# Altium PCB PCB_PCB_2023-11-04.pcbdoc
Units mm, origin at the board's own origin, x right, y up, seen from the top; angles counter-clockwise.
Board outline 154.66 x 127.63 mm, 2 copper layers (Top Layer, Bottom Layer); 91 components, 86 nets, 342 pads, 162 vias.
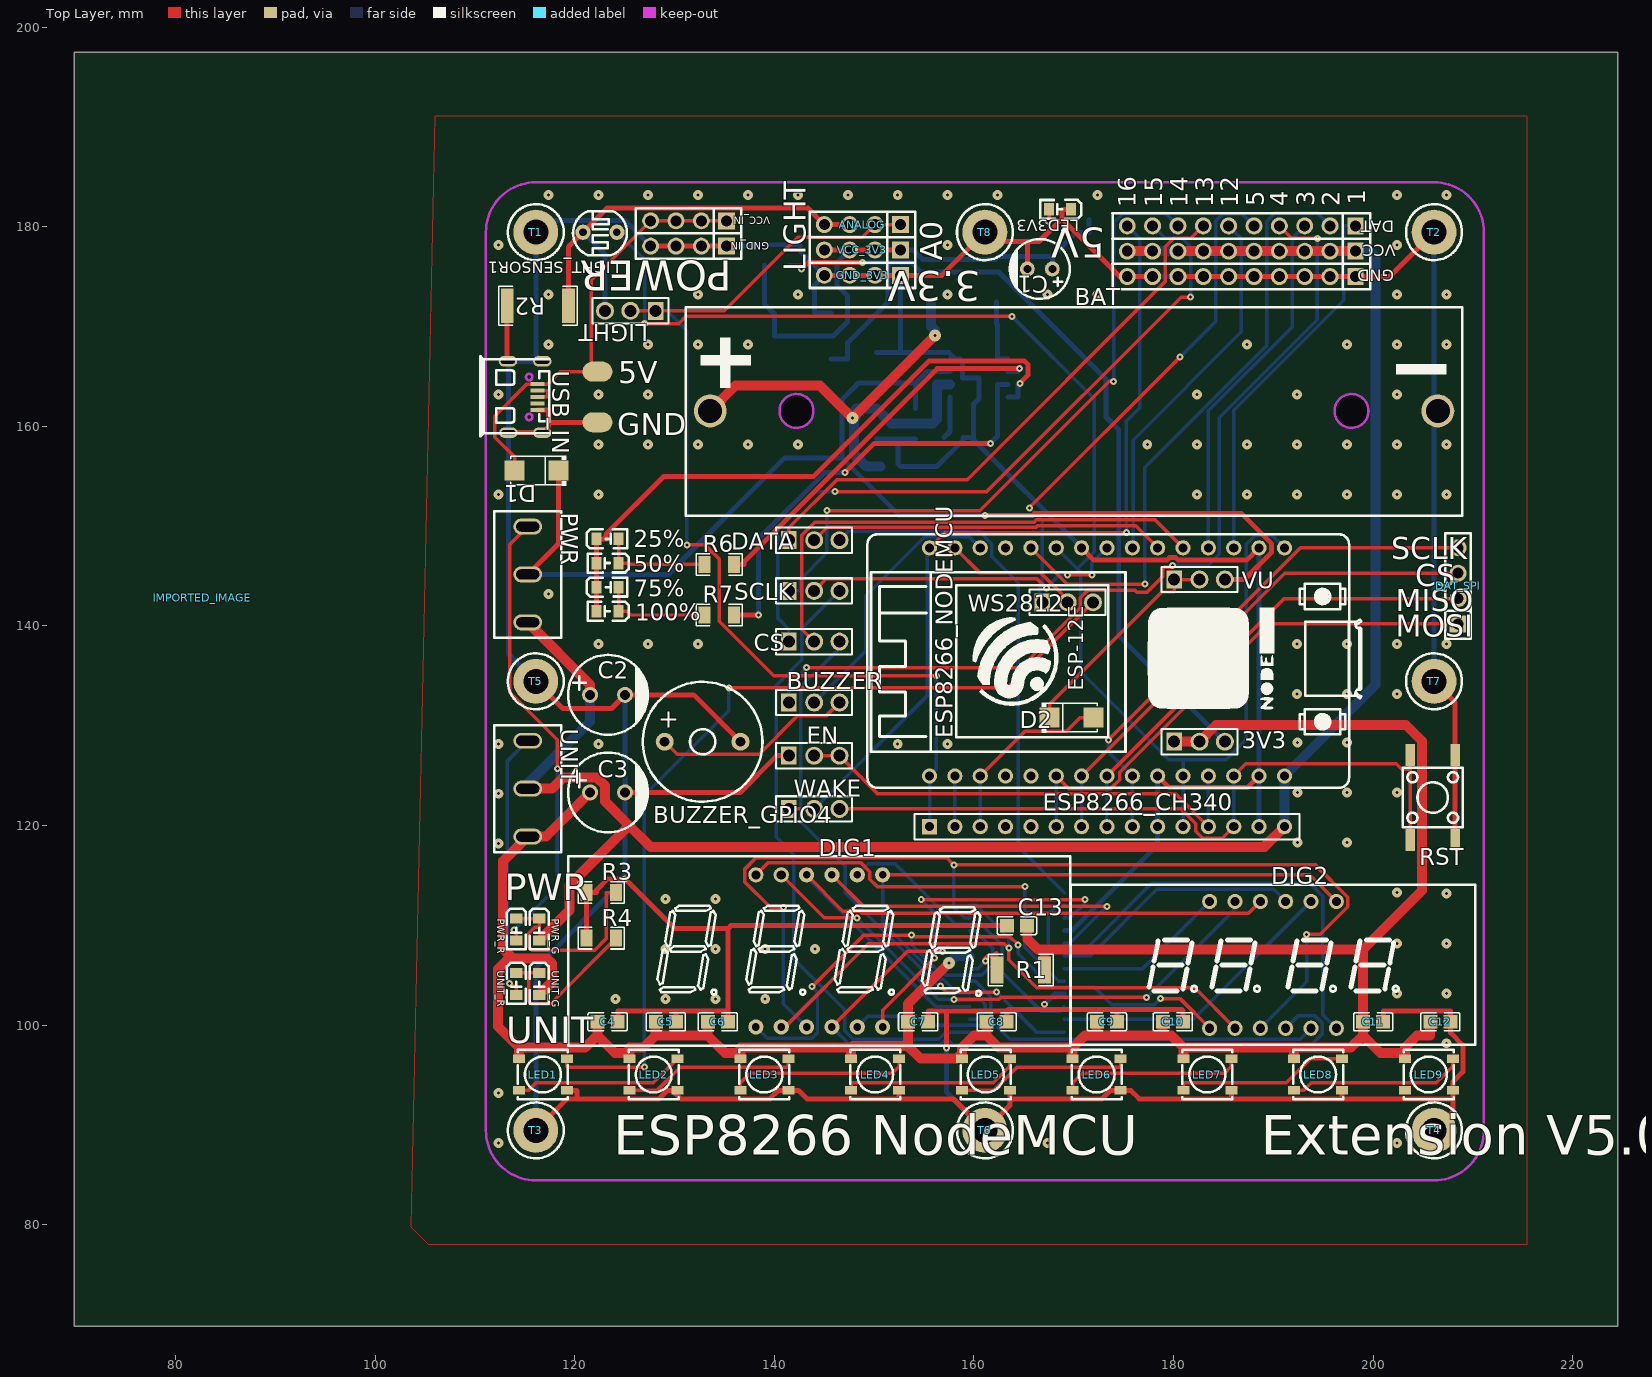
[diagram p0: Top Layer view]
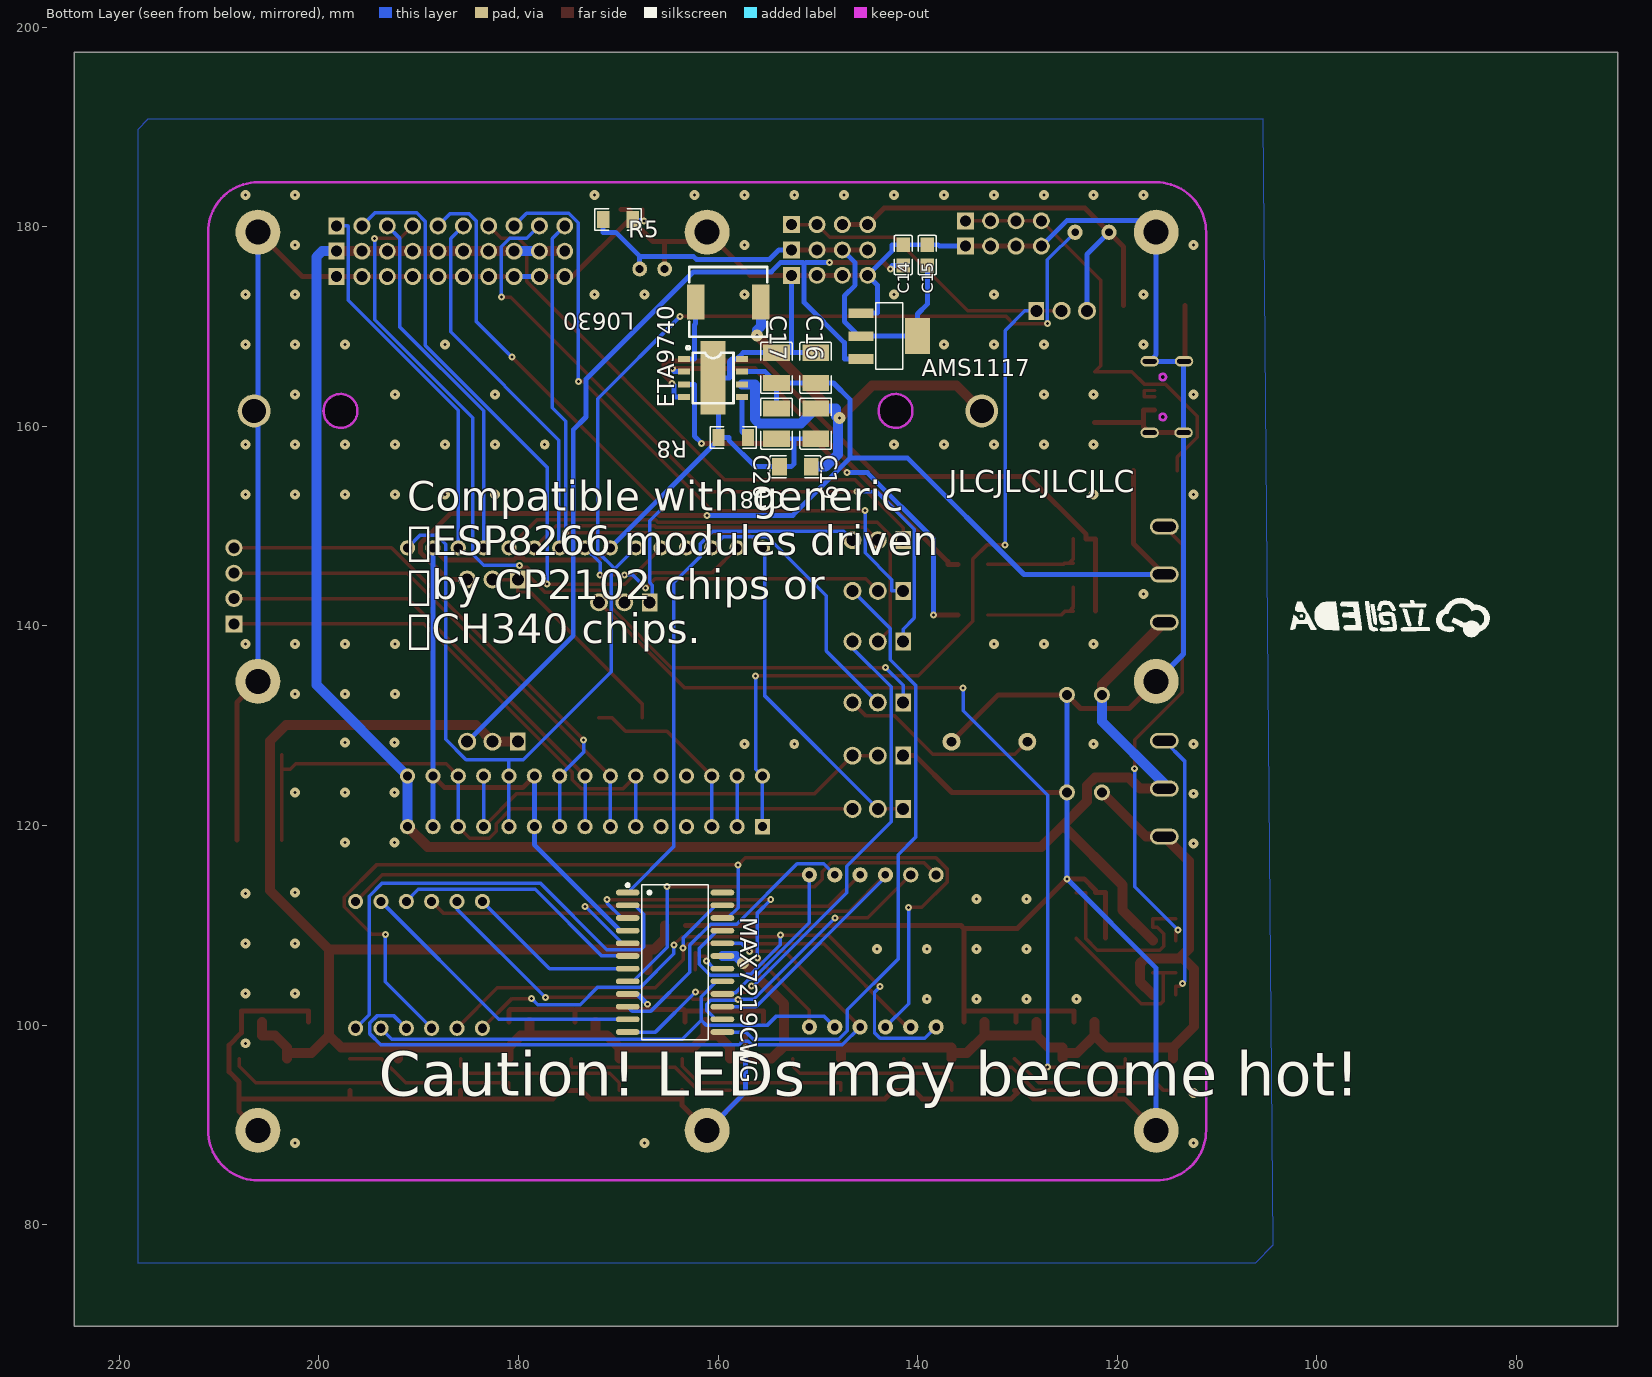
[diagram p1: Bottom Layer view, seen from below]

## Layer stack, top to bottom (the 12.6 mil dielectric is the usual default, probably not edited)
Top Layer: signal copper (thickness not stored)
Dielectric: dielectric 0.32, FR-4, Dk 4.8
Bottom Layer: signal copper (thickness not stored)

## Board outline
224.507,69.85 69.85,69.85 69.85,197.485 224.507,197.485

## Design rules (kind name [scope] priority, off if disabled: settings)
Clearance Default [All] p1: gap=0.178 ignorepadtopadclearanceinfootprint=FALSE except(0: Region-Region Region-Text Text-Text; 0.152: Track-Track Track-SMDPad SMDPad-SMDPad Track-THPad SMDPad-THPad THPad-THPad Track-Via SMDPad-Via THPad-Via Via-Via Track-Fill SMDPad-Fill THPad-Fill Via-Fill Fill-Fill Track-Region SMDPad-Region THPad-Region Via-Region Fill-Region Track-Poly SMDPad-Poly THPad-Poly Via-Poly Fill-Poly Region-Poly Poly-Poly Track-Text SMDPad-Text THPad-Text Via-Text Fill-Text Poly-Text Track-Sheet SMDPad-Sheet THPad-Sheet Via-Sheet Fill-Sheet Region-Sheet Poly-Sheet Text-Sheet Track-Hole SMDPad-Hole THPad-Hole Via-Hole Fill-Hole Region-Hole Poly-Hole Text-Hole Sheet-Hole)
Clearance Power [All] p1: gap=0.178 ignorepadtopadclearanceinfootprint=FALSE except(0: Region-Region Region-Text Text-Text; 0.152: Track-Sheet SMDPad-Sheet THPad-Sheet Via-Sheet Fill-Sheet Region-Sheet Poly-Sheet Text-Sheet Sheet-Hole; 0.16: Track-Track Track-SMDPad SMDPad-SMDPad Track-THPad SMDPad-THPad THPad-THPad Track-Via SMDPad-Via THPad-Via Via-Via Track-Fill SMDPad-Fill THPad-Fill Via-Fill Fill-Fill Track-Region SMDPad-Region THPad-Region Via-Region Fill-Region Track-Poly SMDPad-Poly THPad-Poly Via-Poly Fill-Poly Region-Poly Poly-Poly Track-Text SMDPad-Text THPad-Text Via-Text Fill-Text Poly-Text Track-Hole SMDPad-Hole THPad-Hole Via-Hole Fill-Hole Region-Hole Poly-Hole Text-Hole)
Clearance Wide [All] p1: gap=0.178 ignorepadtopadclearanceinfootprint=FALSE except(0: Region-Region Region-Text Text-Text; 0.152: Track-Sheet SMDPad-Sheet THPad-Sheet Via-Sheet Fill-Sheet Region-Sheet Poly-Sheet Text-Sheet Sheet-Hole; 0.18: Track-Track Track-SMDPad SMDPad-SMDPad Track-THPad SMDPad-THPad THPad-THPad Track-Via SMDPad-Via THPad-Via Via-Via Track-Fill SMDPad-Fill THPad-Fill Via-Fill Fill-Fill Track-Region SMDPad-Region THPad-Region Via-Region Fill-Region Track-Poly SMDPad-Poly THPad-Poly Via-Poly Fill-Poly Region-Poly Poly-Poly Track-Text SMDPad-Text THPad-Text Via-Text Fill-Text Poly-Text Track-Hole SMDPad-Hole THPad-Hole Via-Hole Fill-Hole Region-Hole Poly-Hole Text-Hole)
DiffPairsRouting differentialPair [All] p1: maxuncoupledlength=10 minlimit=6 maxlimit=50 mostfreqgap=6 toplayer_minwidth=5 toplayer_prefwidth=10 toplayer_maxwidth=100 bottomlayer_minwidth=5 bottomlayer_prefwidth=10 bottomlayer_maxwidth=100
PasteMaskExpansion Common [All] p1:
PlaneConnect Default [All] p1: planeconnectstyle=Relief reliefexpansion=0.508 reliefentries=4 reliefconductorwidth=0 reliefairgap=0.254
PlaneConnect Power [All] p1: planeconnectstyle=Relief reliefexpansion=0.508 reliefentries=4 reliefconductorwidth=0 reliefairgap=0.254
PlaneConnect Wide [All] p1: planeconnectstyle=Relief reliefexpansion=0.508 reliefentries=4 reliefconductorwidth=0 reliefairgap=0.254
PolygonConnect gge880165 [All] p1: connectstyle=Relief reliefentries=4 polygonreliefangle="90 Angle" airgapwidth=10
PolygonConnect gge880153 [All] p1: connectstyle=Relief reliefentries=4 polygonreliefangle="90 Angle" airgapwidth=10
RoutingVias Default [All] p1: viastyle="Through Hole" holewidth=11.811 minholewidth=11.811 maxholewidth=2362 width=27.559 minwidth=27.559 maxwidth=3938
RoutingVias Power [All] p1: viastyle="Through Hole" holewidth=11.811 minholewidth=11.811 maxholewidth=2362 width=27.559 minwidth=27.559 maxwidth=3938
RoutingVias Wide [All] p1: viastyle="Through Hole" holewidth=11.811 minholewidth=11.811 maxholewidth=2362 width=47.244 minwidth=47.244 maxwidth=3938
SolderMaskExpansion Common [All] p1: useseparateexpansions=TRUE expansion=2 expansionbottom=2
Width Default [All] p1: maxlimit=1000 minlimit=14 preferedwidth=14
Width Power [All] p1: maxlimit=1000 minlimit=20 preferedwidth=20
Width Wide [All] p1: maxlimit=1000 minlimit=39 preferedwidth=39

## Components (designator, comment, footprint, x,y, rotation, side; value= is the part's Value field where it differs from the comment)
3V3 "Header-Male-2.54_1x3" HDR-TH_3P-P2.54-V-M-1 182.597,128.403 r0 top
25% "LTST-C171KFKT" LED0805-RD_ORANGE 123.288,148.717 r0 top
50% "LTST-C171KFKT" LED0805-RD_ORANGE 123.288,146.304 r180 top
75% "LTST-C171KFKT" LED0805-RD_ORANGE 123.288,143.891 r0 top
100% "LTST-C171KFKT" LED0805-RD_ORANGE 123.288,141.478 r180 top
AMS1117 "AMS1117-3.3V" SOT-223-4_L6.5-W3.5-P2.30-LS7.0-BR 142.846,169.037 r0 bottom
ANALOG "PH-00316" HDR-TH_4P-P2.54-V-M 148.815,180.213 r180 top
BAT "18650 电池盒 插件 1节" BAT-TH_18650-C9900004923 170.024,161.544 r0 top
BUZZER "Header-Male-2.54_1x3" HDR-TH_3P-P2.54-V-M-1 143.989,132.334 r0 top
BUZZER_GPIO4 "TMB12A05" BUZ-TH_BD12.0-P7.60-D0.6-FD 132.813,128.397 r0 top
C1 "100uF" CAP-TH_BD6.0-P2.50-D0.5-FD 166.595,175.768 r180 top
C2 "1000uF" CAP-TH_BD8.0-P3.50-D0.6-FD 123.288,133.096 r0 top
C3 "1000uF" CAP-TH_BD8.0-P3.50-D0.6-FD 123.288,123.317 r0 top
C4 "100nF" C0805#1 123.288,100.33 r0 top
C5 "100nF" C0805#1 129.13,100.33 r0 top
C6 "100nF" C0805#1 134.337,100.33 r0 top
C7 "100nF" C0805#1 154.403,100.33 r0 top
C8 "100nF" C0805#1 162.277,100.33 r0 top
C9 "100nF" C0805#1 173.326,100.33 r0 top
C10 "100nF" C0805#1 179.93,100.33 r0 top
C11 "100nF" C0805#1 199.996,100.33 r0 top
C12 "100nF" C0805#1 206.727,100.33 r0 top
C13 "100nF" C0805#1 164.309,109.982 r0 top
C14 "100nF" C0805#2 141.449,177.165 r90 bottom
C15 "100nF" C0805#2 139.036,177.165 r90 bottom
C16 "22uF" C1210 150.212,165.862 r270 bottom
C17 "22uF" C1210 154.149,165.862 r270 bottom
C18 "4.7uF" C1206 152.244,155.956 r180 bottom
C19 "10uF" C1210 150.212,160.274 r90 bottom
C20 "10uF" C1210 154.149,160.274 r270 bottom
CS "Header-Male-2.54_1x3" HDR-TH_3P-P2.54-V-M-1 143.989,138.43 r0 top
D1 "SS34-A" SMA_L4.3-W2.6-LS5.2-RD 116.176,155.575 r180 top
D2 "SS34-A" SMA_L4.3-W2.6-LS5.2-RD 169.77,130.81 r0 top
DAT "PZ254-1-10-Z-8.5" HDR-TH_10P-P2.54-V-M 186.788,180.086 r180 top
DAT_SPI "PH-00316" HDR-TH_4P-P2.54-V-M 208.505,144.018 r90 top
DATA "Header-Male-2.54_1x3" HDR-TH_3P-P2.54-V-M-1 143.989,148.59 r0 top
DIG1 "FJ5461AH" LED-SEG-TH_12P-L50.3-W19.0-P2.54-S15.24-BL 144.497,107.442 r0 top
DIG2 "SR420401N" LED-SEG-TH_12P-L40.5-W16.0-P2.54-S12.70-BL 189.963,106.045 r0 top
EN "Header-Male-2.54_1x3" HDR-TH_3P-P2.54-V-M-1 143.989,127 r0 top
ESP8266_CH340 "Header-Female-2.54_1x15" HDR-TH_15P-P2.54-V-F-1 173.326,119.888 r0 top
ESP8266_NODEMCU "NodeMCU8266" NODEMCU8266 191.106,124.968 r90 top
ETA9740 "ETA9740" ESOP-8_L4.9-W3.9-P1.27-LS6.0-BL-EP 160.499,164.846 r270 bottom
GND "PZ254-1-10-Z-8.5" HDR-TH_10P-P2.54-V-M 186.788,175.006 r180 top
GND_3V3 "Z-211-0411-0021-001" HDR-TH_4P-P2.54-V-M 148.815,175.133 r180 top
GND_IN "Z-211-0411-0021-001" HDR-TH_4P-P2.54-V-M 131.416,178.054 r180 top
IMPORTED_IMAGE "IMPORTED_IMAGE" IMPORTED_IMAGE 82.691,142.805 r0 top
L0630 "2.2uH" IND-SMD_L7.8-W7.0_FXC0630 158.975,172.466 r180 bottom
LED1 "5050WS2812B" LED-SMD_5050WS2812B 116.811,95.057 r0 top
LED2 "5050WS2812B" LED-SMD_5050WS2812B 127.907,95.057 r0 top
LED3 "5050WS2812B" LED-SMD_5050WS2812B 139.003,95.057 r0 top
LED3V3 "LTST-C171KFKT" LED0805-RD_ORANGE 168.627,181.737 r180 top
LED4 "5050WS2812B" LED-SMD_5050WS2812B 150.099,95.057 r0 top
LED5 "5050WS2812B" LED-SMD_5050WS2812B 161.195,95.057 r0 top
LED6 "5050WS2812B" LED-SMD_5050WS2812B 172.291,95.057 r0 top
LED7 "5050WS2812B" LED-SMD_5050WS2812B 183.387,95.057 r0 top
LED8 "5050WS2812B" LED-SMD_5050WS2812B 194.483,95.057 r0 top
LED9 "5050WS2812B" LED-SMD_5050WS2812B 205.579,95.057 r0 top
LIGHT "Header-Male-2.54_1x3" HDR-TH_3P-P2.54-V-M-1 125.574,171.577 r180 top
LIGHT_SENSOR1 "GL5528(10-20)_C520869" RES-TH_L5.1-W4.3-P3.40-D0.5 122.526,179.451 r90 top
MAX7219CWG "MAX7219CWG" SOIC-24_L15.4-W7.5-P1.27-LS10.3-BL 164.309,106.299 r270 bottom
PWR "SS12D10G5" SS12D10G5 115.287,145.161 r270 top
PWR_G "LTST-C170GKT" LED0805-RD_GREEN 116.43,109.574 r270 top
PWR_R "HL-PSC-2012S9AC-CZ" LED0805-RD_RED 114.144,109.574 r270 top
R1 "220kΩ" R2010 164.69,105.537 r0 top
R2 "10K" R2512 116.303,172.085 r180 top
R3 "10K" R1206 122.653,113.284 r0 top
R4 "10K" R1206 122.653,108.712 r0 top
R5 "10K" R1206 170.024,180.721 r180 bottom
R6 "10K" R1206 134.464,146.177 r0 top
R7 "10K" R1206 134.464,141.097 r0 top
R8 "82kΩ" R1206 158.467,158.877 r180 bottom
RST "K2-1102SP-K4SC-04" KEY-SMD_4P-L6.0-W6.0-P4.50-LS9.5-BL 205.965,122.809 r0 top
SCLK "Header-Male-2.54_1x3" HDR-TH_3P-P2.54-V-M-1 143.989,143.51 r0 top
T1 "M2" TH_BD4.0-D2.0 116.096,179.455 r0 top locked
T2 "M2" TH_BD4.0-D2.0 206.096,179.455 r0 top locked
T3 "M2" TH_BD4.0-D2.0 116.096,89.455 r0 top locked
T4 "M2" TH_BD4.0-D2.0 206.096,89.455 r0 top locked
T5 "M2" TH_BD4.0-D2.0 116.096,134.455 r0 top locked
T6 "M2" TH_BD4.0-D2.0 161.096,89.455 r0 top locked
T7 "M2" TH_BD4.0-D2.0 206.096,134.455 r0 top locked
T8 "M2" TH_BD4.0-D2.0 161.096,179.455 r0 top locked
UNIT "SS12D10G5" SS12D10G5 115.287,123.698 r270 top
UNIT_G "LTST-C170GKT" LED0805-RD_GREEN 116.43,104.14 r270 top
UNIT_R "HL-PSC-2012S9AC-CZ" LED0805-RD_RED 114.144,104.14 r270 top
USB_IN "MICROUSB_5PIN_4DIP" MICRO-USB-SMD_U254-051N-4BH806 115.033,162.941 r270 top
VCC "PZ254-1-10-Z-8.5" HDR-TH_10P-P2.54-V-M 186.788,177.546 r180 top
VCC_3V3 "Z-211-0411-0021-001" HDR-TH_4P-P2.54-V-M 148.815,177.673 r180 top
VCC_IN "Z-211-0411-0021-001" HDR-TH_4P-P2.54-V-M 131.416,180.594 r180 top
VU "Header-Male-2.54_1x3" HDR-TH_3P-P2.54-V-M-1 182.597,144.653 r0 top
WAKE "Header-Male-2.54_1x3" HDR-TH_3P-P2.54-V-M-1 143.989,121.666 r0 top
WS2812 "Header-Male-2.54_1x3" HDR-TH_3P-P2.54-V-M-1 169.389,142.367 r0 top

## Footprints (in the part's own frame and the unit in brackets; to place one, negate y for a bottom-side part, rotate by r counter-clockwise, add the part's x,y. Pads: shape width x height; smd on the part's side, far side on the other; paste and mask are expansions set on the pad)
BAT-TH_18650-C9900004923 [mm]
  round 3.3 hole 2.4: 1(-36.45,0) 2(36.45,0)
  Multi-Layer board cut-out: -26.105,0 -26.273,0.738 -26.745,1.329 -27.427,1.657 -28.183,1.657 -28.865,1.329 -29.337,0.738 -29.505,0 -29.505,0 -29.337,-0.738 -28.865,-1.329 -28.183,-1.657 -27.427,-1.657 -26.745,-1.329 -26.273,-0.738 -26.105,0
  Multi-Layer board cut-out: 29.505,0 29.337,0.738 28.865,1.329 28.183,1.657 27.427,1.657 26.745,1.329 26.273,0.738 26.105,0 26.105,0 26.273,-0.738 26.745,-1.329 27.427,-1.657 28.183,-1.657 28.865,-1.329 29.337,-0.738 29.505,0
  Multi-Layer keep-out circle w0.254: c-27.805,0 r1.7
  Multi-Layer keep-out circle w0.254: c27.805,0 r1.7
  silkscreen extent -38.9,-10.5 38.9,10.4
BUZ-TH_BD12.0-P7.60-D0.6-FD [mm]
  round 1.8 hole 1: 1(-3.8,0) 2(3.8,0)
  silkscreen extent -6,-6 6,6
C0805#1 [mm]
  rect 1.41x1.35 smd: 1(-1,0) 2(1,0)
  silkscreen extent -1.96,-0.9 1.96,0.9
C0805#2 [mm]
  rect 1.41x1.35 smd: 1(-1.03,0) 2(1.03,0)
  silkscreen extent -1.96,-0.9 1.96,0.9
C1206 [mm]
  rect 1.485x1.728 smd: 1(-1.593,0) 2(1.593,0)
  silkscreen extent -2.56,-1.09 2.56,1.09
C1210 [mm]
  rect 1.635x2.7 smd: 1(-1.517,0) 2(1.517,0)
  silkscreen extent -2.56,-1.58 2.56,1.58
CAP-TH_BD6.0-P2.50-D0.5-FD [mm]
  round 1.5 hole 0.8: 1(-1.25,0) 2(1.25,0)
  silkscreen extent -3,-3 3.08,3
CAP-TH_BD8.0-P3.50-D0.6-FD [mm]
  round 1.6 hole 1: 1(-1.75,0) 2(1.75,0)
  silkscreen extent -3.96,-4 4.04,4
ESOP-8_L4.9-W3.9-P1.27-LS6.0-BL-EP [mm]
  rect 0.6x1.2 smd: 1(-1.905,-2.908) 2(-0.635,-2.908) 3(0.635,-2.908) 4(1.905,-2.908) 5(1.905,2.908) 6(0.635,2.908) 7(-0.635,2.908) 8(-1.905,2.908)
  rect 3.3x2.4 smd: 9(0,0)
  silkscreen extent -3.2,-2.67 2.55,2.05
HDR-TH_3P-P2.54-V-M-1 [mm]
  rect 1.575x1.8 hole 1.2: 1(-2.54,0)
  round 1.8 hole 1.2: 2(0,0) 3(2.54,0)
  silkscreen extent -3.81,-1.27 3.81,1.27
HDR-TH_4P-P2.54-V-M [mm]
  rect 1.7x1.7 hole 1.1: 1(-3.81,0)
  round 1.7 hole 1.1: 2(-1.27,0) 3(1.27,0) 4(3.81,0)
  silkscreen extent -5.29,-1.27 5.29,1.27
HDR-TH_10P-P2.54-V-M [mm]
  rect 1.575x1.7 hole 1.1: 1(-11.43,0)
  round 1.7 hole 1.1: 2(-8.89,0) 3(-6.35,0) 4(-3.81,0) 5(-1.27,0) 6(1.27,0) 7(3.81,0) 8(6.35,0) 9(8.89,0) 10(11.43,0)
  silkscreen extent -12.9,-1.27 12.95,1.27
HDR-TH_15P-P2.54-V-F-1 [mil]
  rect 60x60 hole 35.98: 1(-700,0)
  round 60 hole 35.98: 2(-600,0) 3(-500,0) 4(-400,0) 5(-300,0) 6(-200,0) 7(-100,0) 8(0,0) 9(100,0) 10(200,0) 11(300,0) 12(400,0) 13(500,0) 14(600,0) 15(700,0)
  silkscreen extent -760,-50 760,50
IMPORTED_IMAGE [mm]
IND-SMD_L7.8-W7.0_FXC0630 [mm]
  rect 1.75x3.5 smd: 1(-3.277,0) 2(3.277,0)
  silkscreen extent -3.9,-3.5 3.9,3.5
KEY-SMD_4P-L6.0-W6.0-P4.50-LS9.5-BL [mm]
  rect 0.98x2.2 smd: 1(-2.25,-4.275) 2(-2.25,4.275) 3(2.25,-4.275) 4(2.25,4.275)
  silkscreen extent -3,-3 3,3
LED0805-RD_GREEN [mm]
  rect 1x1.25 smd: 1(-1.1,0) 2(1.1,0)
  silkscreen extent -2.1,-0.95 1.98,0.96
LED0805-RD_ORANGE [mm]
  rect 1x1.25 smd: 1(-1.1,0) 2(1.1,0)
  silkscreen extent -2.1,-0.95 1.98,0.96
LED0805-RD_RED [mm]
  rect 1x1.25 smd: 1(-1.1,0) 2(1.1,0)
  silkscreen extent -2.1,-0.95 1.98,0.96
LED-SEG-TH_12P-L40.5-W16.0-P2.54-S12.70-BL [mil]
  round 60 hole 36: 1(-250,-250) 2(-150,-250) 3(-50,-250) 4(50,-250) 5(150,-250) 6(250,-250) 7(250,250) 8(150,250) 9(50,250) 10(-50,250) 11(-150,250) 12(-250,250)
  silkscreen extent -797,-315 797,315
LED-SEG-TH_12P-L50.3-W19.0-P2.54-S15.24-BL [mil]
  round 60 hole 30: 1(-250,-300) 2(-150,-300) 3(-50,-300) 4(50,-300) 5(150,-300) 6(250,-300) 7(250,300) 8(150,300) 9(50,300) 10(-50,300)
  round 60 hole 36: 11(-150,300) 12(-250,300)
  silkscreen extent -990,-374 990,374
LED-SMD_5050WS2812B [mm]
  rect 1.2x0.85 smd: 1(-2.4,1.6) 2(-2.4,-1.6) 3(2.4,-1.6) 4(2.4,1.6)
  silkscreen extent -2.5,-2.5 2.5,2.5
MICRO-USB-SMD_U254-051N-4BH806 [mm]
  rect 0.4x1.4 smd: 1(-1.3,1.225) 2(-0.65,1.225) 3(0,1.225) 4(0.65,1.225) 5(1.3,1.225)
  oval 1.05x1.85 hole 0.45 slot 1.4 at 90 deg: 6(-3.575,1.725) 7(-3.575,-1.725) 8(3.575,1.725) 9(3.575,-1.675)
  Multi-Layer board cut-out: -2,0.73 -2.16,0.684 -2.276,0.566 -2.319,0.405 -2.276,0.244 -2.16,0.126 -2,0.08 -2,0.08 -1.84,0.126 -1.724,0.244 -1.681,0.405 -1.724,0.566 -1.84,0.684 -2,0.73
  Multi-Layer board cut-out: 2,0.73 1.84,0.684 1.724,0.566 1.681,0.405 1.724,0.244 1.84,0.126 2,0.08 2,0.08 2.16,0.126 2.276,0.244 2.319,0.405 2.276,0.566 2.16,0.684 2,0.73
  Multi-Layer keep-out circle w0.254: c-2,0.405 r0.325
  Multi-Layer keep-out circle w0.254: c2,0.405 r0.325
  silkscreen extent -4.06,-4.48 3.94,2.42
NODEMCU8266 [mil]
  round 60 hole 36: 1(0,0) 2(0,100) 3(0,200) 4(0,300) 5(0,400) 6(0,500) 7(0,600) 8(0,700) 9(0,800) 10(0,900) 11(0,1000) 12(0,1100) 13(0,1200) 14(0,1300) 15(0,1400) 16(900,0) 17(900,100) 18(900,200) 19(900,300) 20(900,400) 21(900,500) 22(900,600) 23(900,700) 24(900,800) 25(900,900) 26(900,1000) 27(900,1100) 28(900,1200) 29(900,1300) 30(900,1400)
  silkscreen extent -47,-303 953,1645
R1206 [mm]
  rect 1.208x1.701 smd: 1(-1.479,0) 2(1.479,0)
  silkscreen extent -2.31,-1.08 2.31,1.08
R2010 [mm]
  rect 1.283x2.7 smd: 1(-2.391,0) 2(2.391,0)
  silkscreen extent -3.26,-1.58 3.26,1.58
R2512 [mm]
  rect 1.283x3.456 smd: 1(-3.066,0) 2(3.066,0)
  silkscreen extent -3.94,-1.96 3.94,1.96
RES-TH_L5.1-W4.3-P3.40-D0.5 [mil]
  round 60 hole 30: 1(0,66.93) 2(0,-66.93)
  silkscreen extent -91,-106 83,106
SMA_L4.3-W2.6-LS5.2-RD [mm]
  rect 2x2 smd: 1(-2.2,0) 2(2.2,0)
  silkscreen extent -2.98,-1.5 2.6,1.5
SOIC-24_L15.4-W7.5-P1.27-LS10.3-BL [mm]
  oval 0.574x2.388 smd: 1(-6.985,-4.744) 2(-5.715,-4.744) 3(-4.445,-4.744) 4(-3.175,-4.744) 5(-1.905,-4.744) 6(-0.635,-4.744) 7(0.635,-4.744) 8(1.905,-4.744) 9(3.175,-4.744) 10(4.445,-4.744) 11(5.715,-4.744) 12(6.985,-4.744) 13(6.985,4.744) 14(5.715,4.744) 15(4.445,4.744) 16(3.175,4.744) 17(1.905,4.744) 18(0.635,4.744) 19(-0.635,4.744) 20(-1.905,4.744) 21(-3.175,4.744) 22(-4.445,4.744) 23(-5.715,4.744) 24(-6.985,4.744)
  silkscreen extent -7.87,-4.89 7.78,3.32
SOT-223-4_L6.5-W3.5-P2.30-LS7.0-BR [mm]
  rect 2.47x0.98 smd: 1(2.835,-2.3) 2(2.835,0) 3(2.835,2.3)
  rect 2.47x3.6 smd: 4(-2.835,0)
  silkscreen extent -1.37,-3.33 1.37,3.33
SS12D10G5 [mm]
  oval 1.6x2.9 hole 1 slot 2.3 at 90 deg: 1(-4.8,0) 2(0,0) 3(4.8,0)
  silkscreen extent -6.35,-3.35 6.35,3.35
TH_BD4.0-D2.0 [mm]
  round 4.5 hole 2.5: 1(0,0)
  silkscreen extent -2.8,-2.8 2.8,2.8

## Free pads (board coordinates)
  oval 3x2 smd: 1(122.272,165.481) 2(122.272,160.401)
  rect 2.54x7.366 smd far side: 4(160.499,164.846)

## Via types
v1: diameter 1, hole 0.3, Top Layer to Bottom Layer, 103 vias
v2: diameter 0.7, hole 0.3, Top Layer to Bottom Layer, 56 vias
v3: diameter 1.2, hole 0.3, Top Layer to Bottom Layer, 3 vias

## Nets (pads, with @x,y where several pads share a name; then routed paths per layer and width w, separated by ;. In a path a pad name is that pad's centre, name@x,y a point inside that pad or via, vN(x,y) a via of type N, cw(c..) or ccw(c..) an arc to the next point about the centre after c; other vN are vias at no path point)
75%_2: 75%.2 100%.1 R7.1 | length 11.3
  Top Layer w0.35: 100%.1 100%.1@124.814,141.478 ; 75%.2 124.388,141.903 100%.1@124.814,141.478 ; R7.1 125.62,141.097 125.239,141.478 100%.1@124.814,141.478
AMS1117_2: AMS1117.2 AMS1117.4 C1.1 C15.1 R5.1 VCC_3V3.1 VCC_3V3.2 VCC_3V3.3 VCC_3V3.4 | length 54.1
  Top Layer w0.5: VCC_3V3.4 VCC_3V3.3 VCC_3V3.2 VCC_3V3.1
  Bottom Layer w0.5: C15.1 139.036,172.238 140.011,171.263 140.011,169.037 AMS1117.2 145.877,169.037 147.327,170.486 147.327,173.076 146.265,174.137 146.265,176.393 VCC_3V3.3 ; VCC_3V3.1 153.901,177.673 154.86,176.713 162.144,176.713 162.468,177.038 167.845,177.038 ; C1.1 167.845,177.038 ; R5.1 171.503,179.445 170.252,179.445 167.845,177.038
AMS1117_3: 3V3.3 AMS1117.3 C14.1 | length 91.4
  Top Layer w0.5: v2(142.728,175.753) 143.378,176.403 v2(148.815,176.403)
  Bottom Layer w0.5: C14.1 142.55,176.135 142.55,175.93 v2(142.728,175.753) ; AMS1117.3 146.127,166.737 147.342,166.737 147.342,168.381 151.364,172.404 151.364,176.248 ; v2(148.815,176.403) 151.209,176.403 151.364,176.248 ; 3V3.3 174.507,139.033 174.507,159.667 173.229,160.944 173.229,164.72 162.461,175.488 154.665,175.488 153.759,176.394 151.51,176.394 151.364,176.248
ANALOG_3: ANALOG.3 ANALOG.4 LIGHT.3 LIGHT_SENSOR1.1 R2.1 | length 45.2
  Top Layer w0.5: R2.1 119.369,177.994 LIGHT_SENSOR1.1 123.23,181.855 143.363,181.855 ANALOG.4 ANALOG.3
  Bottom Layer w0.5: LIGHT_SENSOR1.1 123.034,177.243 LIGHT.3
BUZZER_1: BUZZER.1 DAT.4 | length 91.5
  Top Layer w0.35: v2(143.215,135.829) 164.677,135.829 170.658,141.81 170.658,142.836 171.422,143.599 176.09,143.599 176.299,143.39 177.338,143.39 178.941,144.993 178.941,145.689 179.133,145.882 179.707,145.882 v2(179.902,146.077) ; DAT.4 191.849,178.835 v2@194.408,178.835
  Bottom Layer w0.35: BUZZER.1 141.449,134.063 v2(143.215,135.829) ; v2(179.902,146.077) 183.456,146.077 184.578,147.2 184.578,160.859 194.408,170.689 v2@194.408,178.835
  other v2: 194.408,178.835
BUZZER_GPIO4_1: BUZZER.3 BUZZER_GPIO4.1 | length 20.2
  Top Layer w0.35: BUZZER_GPIO4.1 130.255,127.155 138.482,127.155 142.304,130.978 145.173,130.978 BUZZER.3
CS_1: CS.1 DAT.9 | length 72.4
  Top Layer w0.35: v2(146.071,153.471) 161.279,153.471 180.758,172.95 v2@181.708,172.95
  Bottom Layer w0.35: CS.1 141.449,139.681 140.333,140.797 140.333,149.675 144.128,153.471 v2(146.071,153.471) ; DAT.9 179.149,178.835 180.874,178.835 181.708,178.002 v2@181.708,172.95
  other v2: 181.708,172.95
DATA_1: DAT.7 DATA.1 | length 57.4
  Top Layer w0.35: DATA.1 141.449,149.841 146.276,154.668 159.321,154.668 179.168,174.514 179.168,178.001 180.002,178.835 181.727,178.835 DAT.7
DIG1_6: DIG1.6 MAX7219CWG.3 | length 34.9
  Top Layer w0.35: DIG1.6 150.847,101.51 v2(156.051,106.714) ; v2(154.718,112.574) v2(171.102,112.574)
  Bottom Layer w0.35: v2(154.718,112.574) 156.051,111.241 v2(156.051,106.714) ; MAX7219CWG.3 169.653,110.744 171.102,112.193 v2(171.102,112.574)
DIG1_8: DIG1.8 MAX7219CWG.10 | length 29.1
  Bottom Layer w0.35: DIG1.8 149.418,116.173 152.084,116.173 158.129,110.128 160.726,110.128 162.822,108.033 162.822,105.32 166.771,101.371 168.57,101.371 MAX7219CWG.10
DIG1_9: DIG1.9 MAX7219CWG.5 | length 34.7
  Top Layer w0.35: DIG1.9 148.934,111.895 173.298,111.895 v2(173.317,111.914)
  Bottom Layer w0.35: MAX7219CWG.5 169.607,108.204 v2(173.317,111.914)
DIG1_12: DIG1.12 MAX7219CWG.8 | length 40.3
  Top Layer w0.35: DIG1.12 139.338,116.253 148.706,116.253 149.577,115.382 149.577,114.632 150.319,113.889 v2(165.098,113.889)
  Bottom Layer w0.35: v2(165.098,113.889) 165.098,107.799 168.503,104.394 MAX7219CWG.8
DIG2_1: DIG1.1 DIG2.1 MAX7219CWG.21 | length 74.1
  Top Layer w0.35: v2(143.772,103.855) 148.947,109.031 153.747,109.031 153.915,108.863 163.603,108.863 v2(164.419,108.047) ; v2(178.689,102.669) 180.639,102.669 DIG2.1
  Bottom Layer w0.35: DIG1.1 139.271,98.698 143.769,98.698 144.323,99.252 144.323,103.304 v2(143.772,103.855) ; v2@153.747,109.031 153.747,108.057 156.715,105.089 157.118,105.089 157.197,105.01 160.787,105.01 161.889,106.111 161.889,107.686 160.1,109.474 MAX7219CWG.21 ; v2(164.419,108.047) 164.419,107.148 167.789,103.778 172.096,103.778 173.82,102.054 178.073,102.054 v2(178.689,102.669)
  other v2: 153.747,109.031
DIG2_2: DIG1.2 DIG2.2 MAX7219CWG.23 | length 59.4
  Top Layer w0.35: DIG1.2 141.061,99.822 149.414,108.175 163.047,108.175 v2(163.5,107.722) 163.5,106.541 166.304,103.737 182.111,103.737 DIG2.2
  Bottom Layer w0.35: MAX7219CWG.23 160.226,112.014 163.5,108.74 v2(163.5,107.722)
DIG2_3: DIG1.3 DIG2.3 MAX7219CWG.22 | length 105.5
  Top Layer w0.35: v2(140.902,111.807) 139.575,111.807 137.01,114.372 137.01,115.603 138.164,116.757 157.283,116.757 v2(157.99,116.05) 194.225,116.05 197.458,112.817 197.458,111.884 194.677,109.104 v2(193.337,109.104)
  Bottom Layer w0.35: v2(140.902,111.807) 140.902,102.147 DIG1.3 ; v2(157.99,116.05) 157.99,111.78 159.026,110.744 MAX7219CWG.22 ; DIG2.3 193.337,104.339 v2(193.337,109.104)
DIG2_4: DIG1.4 DIG2.4 MAX7219CWG.20 | length 73.4
  Top Layer w0.35: DIG1.4 153.337,107.392 v2(156.843,107.392)
  Bottom Layer w0.35: DIG1.4 147.56,98.029 156.636,98.029 156.981,98.374 157.548,98.374 157.893,98.029 193.785,98.029 194.872,99.116 194.872,100.224 194.173,100.923 192.461,100.923 DIG2.4 ; v2(156.843,107.392) 157.655,108.204 MAX7219CWG.20
DIG2_5: DIG1.5 DIG2.5 MAX7219CWG.17 | length 52.9
  Bottom Layer w0.35: DIG1.5 149.399,100.914 154.145,100.914 155.09,99.968 161.154,99.968 161.696,100.511 ; MAX7219CWG.17 160.154,104.394 161.696,102.851 161.696,100.511 ; DIG2.5 192.682,98.604 163.603,98.604 161.696,100.511
DIG2_6: DIG2.6 MAX7219CWG.2 | length 49.9
  Bottom Layer w0.35: MAX7219CWG.2 168.335,112.014 167.447,111.126 167.447,107.856 167.734,107.569 171.132,107.569 177.76,114.197 193.682,114.197 194.949,112.929 194.949,101.059 DIG2.6
DIG2_7: DIG1.7 DIG2.7 MAX7219CWG.16 | length 63.1
  Top Layer w0.35: DIG1.7 193.646,115.062 DIG2.7
  Bottom Layer w0.35: DIG1.7 150.847,110.245 156.507,104.586 156.909,104.586 158.226,103.269 159.42,103.269 MAX7219CWG.16
DIG2_8: DIG2.8 MAX7219CWG.11 | length 29.6
  Bottom Layer w0.35: MAX7219CWG.11 181.962,100.584 DIG2.8
DIG2_9: DIG2.9 MAX7219CWG.6 | length 25.4
  Bottom Layer w0.35: MAX7219CWG.6 171.643,106.934 178.316,113.607 190.021,113.607 DIG2.9
DIG2_10: DIG1.10 DIG2.10 MAX7219CWG.15 | length 69.5
  Top Layer w0.35: DIG1.10 146.861,111.428 148.544,111.428 148.738,111.234 187.532,111.234 DIG2.10
  Bottom Layer w0.35: DIG1.10 143.227,114.826 156.199,101.854 MAX7219CWG.15
DIG2_11: DIG1.11 DIG2.11 MAX7219CWG.14 | length 61
  Top Layer w0.35: DIG1.11 145,110.749 v2(148.263,110.749) ; v2(158,102.59) 162.523,102.59 162.714,102.782 v2(177.31,102.782)
  Bottom Layer w0.35: v2(148.263,110.749) 156.422,102.59 v2(158,102.59) 158.101,102.489 160.715,102.489 161.153,102.052 161.153,101.489 160.248,100.584 MAX7219CWG.14 ; v2(177.31,102.782) 186.153,111.625 DIG2.11
DIG2_12: DIG2.12 MAX7219CWG.7 | length 17.3
  Bottom Layer w0.35: MAX7219CWG.7 176.882,105.664 DIG2.12
ESP8266_CH340_4: ESP8266_CH340.4
ESP8266_CH340_5: ESP8266_CH340.5
ESP8266_NODEMCU_1: C2.1 ESP8266_CH340.15 ESP8266_NODEMCU.1 PWR.3 PWR_G.2 UNIT.2 VCC.1 VCC.2 VCC.3 VCC.4 VCC.5 VCC.6 VCC.7 VCC.8 VCC.9 VCC.10 | length 204
  Top Layer w1: UNIT.2 117.716,123.698 118.816,124.798 122.237,124.798 123.025,124.01 123.025,122.433 125.441,120.017 ; PWR.3 121.538,134.11 C2.1 ; PWR_G.2 119.491,111.534 119.491,114.066 125.441,120.017 ; VCC.10 VCC.9 ; VCC.8 VCC.7 VCC.6 VCC.5 VCC.4 VCC.3 VCC.2 VCC.1 ; ESP8266_CH340.15 189.091,117.873 127.585,117.873 125.441,120.017
  Bottom Layer w1: UNIT.2 115.287,124.185 121.538,130.436 C2.1 ; VCC.9 VCC.8 ; ESP8266_CH340.15 ESP8266_NODEMCU.1 200.244,134.106 200.244,176.988 199.686,177.546 VCC.1
ESP8266_NODEMCU_3: ESP8266_CH340.13 ESP8266_NODEMCU.3 RST.1 RST.2 WAKE.3 | length 73.7
  Top Layer w0.35: WAKE.3 180.746,121.666 182.216,120.196 182.216,119.447 182.925,118.738 184.876,118.738 ESP8266_CH340.13 ; ESP8266_NODEMCU.3 187.236,126.178 202.33,126.178 202.874,125.633 203.715,125.633 ; RST.1 203.715,125.633 ; RST.2 203.715,125.633
  Bottom Layer w0.35: ESP8266_CH340.13 ESP8266_NODEMCU.3
ESP8266_NODEMCU_4: EN.2 EN.3 ESP8266_CH340.12 ESP8266_NODEMCU.4 | length 47.5
  Top Layer w0.35: EN.2 EN.3 150.322,123.207 180.167,123.207 ESP8266_CH340.12
  Bottom Layer w0.35: ESP8266_CH340.12 ESP8266_NODEMCU.4
ESP8266_NODEMCU_7: DAT_SPI.4 ESP8266_CH340.9 ESP8266_NODEMCU.7 | length 52.7
  Top Layer w0.35: v2(173.465,128.574) 192.719,147.828 DAT_SPI.4
  Bottom Layer w0.35: v2(173.465,128.574) 173.465,127.369 ESP8266_NODEMCU.7 ESP8266_CH340.9
ESP8266_NODEMCU_8: DAT_SPI.2 ESP8266_CH340.8 ESP8266_NODEMCU.8 | length 47.6
  Top Layer w0.35: ESP8266_NODEMCU.8 191.106,142.748 DAT_SPI.2
  Bottom Layer w0.35: ESP8266_CH340.8 ESP8266_NODEMCU.8
ESP8266_NODEMCU_9: DAT_SPI.3 ESP8266_CH340.7 ESP8266_NODEMCU.9 | length 51.2
  Top Layer w0.35: ESP8266_NODEMCU.9 170.819,124.968 191.139,145.288 DAT_SPI.3
  Bottom Layer w0.35: ESP8266_CH340.7 ESP8266_NODEMCU.9
ESP8266_NODEMCU_10: DAT_SPI.1 ESP8266_CH340.6 ESP8266_NODEMCU.10 | length 53.1
  Top Layer w0.35: ESP8266_NODEMCU.10 169.503,123.711 173.705,123.711 174.596,124.601 174.596,125.326 189.478,140.208 DAT_SPI.1
  Bottom Layer w0.35: ESP8266_CH340.6 ESP8266_NODEMCU.10
ESP8266_NODEMCU_11: ESP8266_NODEMCU.11
ESP8266_NODEMCU_12: ESP8266_NODEMCU.12
ESP8266_NODEMCU_13: D2.2 ESP8266_CH340.3 ESP8266_NODEMCU.13 | length 18.8
  Top Layer w0.35: ESP8266_NODEMCU.13 165.117,129.459 169.268,129.459 170.619,130.81 D2.2
  Bottom Layer w0.35: ESP8266_CH340.3 ESP8266_NODEMCU.13
ESP8266_NODEMCU_14: ESP8266_CH340.2 ESP8266_NODEMCU.14 | length 5.1
  Bottom Layer w0.35: ESP8266_CH340.2 ESP8266_NODEMCU.14
ESP8266_NODEMCU_15: ANALOG.1 ANALOG.2 ESP8266_CH340.1 ESP8266_NODEMCU.15 LIGHT.1 LIGHT.2 | length 105.5
  Top Layer w0.35: LIGHT.2 LIGHT.1 134.965,171.577 142.331,178.943 148.815,178.943 ANALOG.2 151.424,180.213 ANALOG.1 ; v2(131.229,148.114) 133.05,148.114 134.461,146.703 134.461,140.482 139.936,135.007 v2(156.222,135.007)
  Bottom Layer w0.35: LIGHT.1 129.252,171.577 131.229,169.6 v2(131.229,148.114) ; ESP8266_CH340.1 ESP8266_NODEMCU.15 156.222,125.644 v2(156.222,135.007)
ESP8266_NODEMCU_18: DAT.1 ESP8266_NODEMCU.18 | length 38
  Bottom Layer w0.35: ESP8266_NODEMCU.18 186.026,161.594 197.054,172.622 197.054,180.06 197.08,180.086 DAT.1
ESP8266_NODEMCU_19: DAT.3 ESP8266_NODEMCU.19 | length 36.3
  Bottom Layer w0.35: ESP8266_NODEMCU.19 183.486,161.546 191.868,169.928 191.868,178.816 DAT.3
ESP8266_NODEMCU_20: CS.2 ESP8266_NODEMCU.20 | length 51.2
  Top Layer w0.35: CS.2 142.743,139.676 142.743,149.101 144.049,150.406 166.023,150.406 166.25,150.633 178.141,150.633 ESP8266_NODEMCU.20
ESP8266_NODEMCU_21: DATA.2 ESP8266_NODEMCU.21 | length 35.9
  Top Layer w0.35: DATA.2 145.301,149.902 166.232,149.902 166.363,150.033 176.201,150.033 ESP8266_NODEMCU.21
ESP8266_NODEMCU_22: DAT.6 ESP8266_NODEMCU.22 | length 37.3
  Bottom Layer w0.35: ESP8266_NODEMCU.22 175.946,147.908 175.946,158.617 186.787,169.459 186.787,178.817 DAT.6
ESP8266_NODEMCU_23: ESP8266_NODEMCU.23 SCLK.2 | length 32.6
  Top Layer w0.35: SCLK.2 145.218,144.739 166.314,144.739 v2(167.254,143.799) ; v2(169.392,145.109) v2(171.82,145.109)
  Bottom Layer w0.35: v2(167.254,143.799) 168.564,145.109 v2(169.392,145.109) ; v2(171.82,145.109) 171.82,146.322 ESP8266_NODEMCU.23
ESP8266_NODEMCU_25: ESP8266_CH340.11 ESP8266_NODEMCU.5 ESP8266_NODEMCU.16 ESP8266_NODEMCU.25 LIGHT_SENSOR1.2 | length 142.3
  Top Layer w0.35: v2(126.998,170.287) 130.405,170.287 131.124,171.006 v2(163.806,171.006)
  Bottom Layer w0.35: LIGHT_SENSOR1.2 126.998,176.679 v2(126.998,170.287) ; v2(163.806,171.006) 172.061,162.752 172.061,147.413 170.361,145.713 ; ESP8266_NODEMCU.25 170.361,145.713 ; ESP8266_CH340.11 ESP8266_NODEMCU.5 180.946,126.603 ; ESP8266_NODEMCU.16 189.865,149.069 188.189,149.069 187.291,148.172 187.291,128.647 185.248,126.603 180.946,126.603 ; 170.361,145.713 170.7,145.374 170.7,135.418 179.515,126.603 180.946,126.603
ESP8266_NODEMCU_26: DAT.2 ESP8266_NODEMCU.26 | length 61.6
  Top Layer w0.35: ESP8266_NODEMCU.26 169.35,144.184 v2(177.136,144.184)
  Bottom Layer w0.35: v2(177.136,144.184) 177.136,155.909 189.328,168.101 189.328,180.53 190.188,181.39 194.374,181.39 DAT.2
ESP8266_NODEMCU_27: ESP8266_NODEMCU.27
ESP8266_NODEMCU_28: BUZZER.2 ESP8266_NODEMCU.28 | length 27.2
  Bottom Layer w0.35: BUZZER.2 149.15,137.495 149.15,143.042 155.064,148.956 159.498,148.956 ESP8266_NODEMCU.28
ESP8266_NODEMCU_29: ESP8266_NODEMCU.29 WS2812.2 | length 13.7
  Top Layer w0.35: ESP8266_NODEMCU.29 160.607,145.307 166.706,145.307 169.389,142.624 WS2812.2
ESP8266_NODEMCU_30: DAT.10 ESP8266_NODEMCU.30 WAKE.1 WAKE.2 | length 85.7
  Top Layer w0.35: WAKE.1 WAKE.2 ; ESP8266_NODEMCU.30 157.073,149.355 v2(175.267,149.355)
  Bottom Layer w0.35: WAKE.2 155.299,132.976 155.299,147.581 ESP8266_NODEMCU.30 ; v2(175.267,149.355) 175.267,160.495 176.628,161.856 176.628,178.816 DAT.10
ETA9740_1: ETA9740.1 L0630.1 | length 6.8
  Bottom Layer w0.5: L0630.1 162.252,170.29 162.382,170.161 162.382,166.751 ETA9740.1
ETA9740_2: ETA9740.2 R6.2 | length 38.3
  Top Layer w0.5: R6.2 136.972,146.177 136.972,146.434 156.31,165.772 v2(164.583,165.772)
  Bottom Layer w0.5: ETA9740.2 164.433,165.481 164.433,165.622 v2(164.583,165.772)
ETA9740_3: ETA9740.3 R7.2 | length 44.5
  Top Layer w0.5: R7.2 v2(138.402,141.097) ; v2@147.065,155.353 150.01,158.299 v2(161.647,158.299)
  Bottom Layer w0.5: v2(138.402,141.097) 138.402,148.715 145.039,155.353 v2@147.065,155.353 ; v2(161.647,158.299) 162.382,159.033 162.382,164.211 ETA9740.3
  other v2: 147.065,155.353
ETA9740_4: 25%.1 50%.2 75%.1 100%.2 ETA9740.4 | length 63
  Top Layer w0.5: 100%.2@122.188,141.478 122.188,143.891 122.188,146.304 122.188,148.717 123.114,148.717 123.114,149.18 128.887,154.953 143.9,154.953 155.507,166.56 165.045,166.56 165.432,166.173 165.432,165.156 v2(164.589,164.314)
  Bottom Layer w0.5: ETA9740.4 164.433,162.941 164.433,164.158 v2(164.589,164.314)
ETA9740_5: ETA9740.5 R8.2 | length 4.3
  Bottom Layer w0.5: R8.2 157.591,159.479 ETA9740.5
ETA9740_6: BAT.1 C18.2 C19.2 ETA9740.6 L0630.2 | length 53.6
  Top Layer w1: BAT.1 136.11,164.08 144.557,164.08 v3(147.821,160.816) 147.821,160.85 v3(156.081,169.11)
  Bottom Layer w1: v3(147.821,160.816) v3@148.001,160.816 ; C18.2 149.228,155.956 148.001,157.183 v3@148.001,160.816 ; L0630.2 155.698,170.035 156.081,169.652 v3(156.081,169.11) ; ETA9740.6 156.31,164.211 156.31,160.719 155.884,160.293 151.71,160.293 C19.2 148.181,161.791 148.181,160.996 v3@148.001,160.816
GND: 
LED1_2: LED1.2 LED2.4 | length 17.2
  Top Layer w0.35: LED1.2 115.362,93.457 116.122,94.217 127.868,94.217 LED2.4
LED1_4: LED1.4 WS2812.3 | length 90.1
  Top Layer w0.35: LED1.4@119.211,96.657 119.211,95.881 119.302,95.79 v2(126.977,95.79) ; v2(135.438,133.786) 163.348,133.786 WS2812.3
  Bottom Layer w0.35: v2(126.977,95.79) 126.977,123.032 135.438,131.494 v2(135.438,133.786)
LED2_2: LED2.2 LED3.4 | length 17.7
  Top Layer w0.35: LED2.2 128.24,93.457 130.584,95.801 141.323,95.801 141.403,95.881 LED3.4@141.403,96.657
LED3_2: LED3.2 LED4.4 | length 18.1
  Top Layer w0.35: LED3.2 136.603,94.233 137.566,95.196 151.814,95.196 152.499,95.881 LED4.4
LED3V3_2: LED3V3.2 R5.2 | length 2.4
  Top Layer w0.35: v2(167.426,180.592) 167.426,180.661 167.527,180.761 LED3V3.2@167.527,181.737
  Bottom Layer w0.35: v2(167.426,180.592) 167.556,180.721 167.591,180.721 R5.2
LED4_2: LED4.2 LED5.4 | length 18.1
  Top Layer w0.35: LED4.2 147.699,94.233 161.947,94.233 163.595,95.881 LED5.4@163.595,96.657
LED5_2: LED5.2 LED6.4 | length 17.7
  Top Layer w0.35: LED5.2 161.965,93.457 164.309,95.801 174.611,95.801 174.691,95.881 LED6.4
LED6_2: LED6.2 LED7.4 | length 18.1
  Top Layer w0.35: LED6.2 169.891,94.233 170.854,95.196 185.102,95.196 185.787,95.881 LED7.4@185.787,96.657
LED7_2: LED7.2 LED8.4 | length 17.7
  Top Layer w0.35: LED7.2 180.987,94.233 191.305,94.233 193.73,96.657 LED8.4
LED8_2: LED8.2 LED9.4 | length 17.7
  Top Layer w0.35: LED8.2 193.034,93.457 193.794,94.217 206.315,94.217 207.979,95.881 LED9.4@207.979,96.657
LED9_2: LED9.2
MAX7219CWG_1: DATA.3 MAX7219CWG.1 | length 54.1
  Bottom Layer w0.35: DATA.3 147.416,149.477 160.522,149.477 161.76,148.24 161.76,146.986 164.436,144.31 164.436,117.901 MAX7219CWG.1
MAX7219CWG_12: CS.3 MAX7219CWG.12 | length 56.3
  Top Layer w0.35: v2(156.628,103.907) 157.229,103.306 v2(162.279,103.306)
  Bottom Layer w0.35: CS.3 146.529,137.772 142.663,133.906 142.663,120.369 147.12,115.912 147.12,113.26 156.473,103.907 v2(156.628,103.907) ; v2(162.279,103.306) 166.271,99.314 MAX7219CWG.12
MAX7219CWG_13: MAX7219CWG.13 SCLK.3 | length 62.7
  Bottom Layer w0.35: SCLK.3 142.76,139.741 142.76,136.607 140.214,134.061 140.214,118.817 141.957,117.074 141.957,106.629 147.037,101.549 147.037,99.426 147.891,98.572 156.467,98.572 157.209,99.314 MAX7219CWG.13
MAX7219CWG_18: MAX7219CWG.18 R1.1 | length 5.3
  Top Layer w0.35: v2(161.154,106.424) 161.154,106.746 161.299,106.891 161.861,106.891 162.209,107.238 162.299,107.238 R1.1
  Bottom Layer w0.35: MAX7219CWG.18 160.394,105.664 v2(161.154,106.424)
MAX7219CWG_24: MAX7219CWG.24
PWR_1: PWR.1 PWR_R.2 | length 46.1
  Top Layer w0.35: v2(113.937,109.557) 114.144,109.35 PWR_R.2 ; PWR.1 113.481,148.155 113.481,133.37 118.253,128.599 v2(118.253,125.693)
  Bottom Layer w0.35: v2(113.937,109.557) 118.253,113.873 v2(118.253,125.693)
PWR_2: C16.2 C17.2 C20.1 D1.1 ETA9740.7 PWR.2 VU.3 | length 121.9
  Top Layer w0.5: PWR.2 118.376,148.25 D1.1 ; v2(161.098,151.091) 161.12,151.069 165.858,151.069 166.075,151.285 186.787,151.285 189.836,148.236 189.836,147.384 187.105,144.653 VU.3@185.137,144.653
  Bottom Layer w0.5: PWR.2 129.352,145.161 141,156.809 146.791,156.809 ; C20.1 C17.2 ; ETA9740.7 155.285,165.481 C17.2 ; v2(161.098,151.091) 152.508,151.091 146.791,156.809 ; 146.791,156.809 146.791,162.699 148.436,164.345 C16.2 151.988,164.345 C17.2
PWR_R_1: PWR_G.1 PWR_R.1 R3.2 | length 19.7
  Top Layer w0.35: PWR_R.1@114.144,110.674 116.43,110.674 116.43,109.824 116.005,109.824 115.353,109.171 115.353,107.924 115.752,107.525 121.988,107.525 123.177,108.714 123.177,113.284 R3.2
R6_1: 25%.2 50%.1 R6.1 | length 11.2
  Top Layer w0.35: 50%.1 50%.1@124.814,146.304 ; 25%.2 124.388,146.729 50%.1@124.814,146.304 ; R6.1 125.366,146.177 125.239,146.304 50%.1@124.814,146.304
SCLK_1: DAT.8 SCLK.1 | length 67.6
  Top Layer w0.35: v2(145.259,151.549) 160.587,151.549 173.543,164.505 v2(173.99,164.505)
  Bottom Layer w0.35: SCLK.1 142.587,143.51 142.587,144.648 145.259,147.32 v2(145.259,151.549) ; v2(173.99,164.505) 173.99,180.386 174.94,181.336 179.188,181.336 DAT.8
UNIT_1: UNIT.1 UNIT_R.2 | length 26.9
  Top Layer w0.35: v2(113.443,104.198) 113.75,103.891 114.144,103.891 UNIT_R.2
  Bottom Layer w0.35: v2(113.443,104.198) 113.258,104.382 113.258,126.469 UNIT.1
UNIT_R_1: R4.2 UNIT_G.1 UNIT_R.1 | length 16.7
  Top Layer w0.35: UNIT_R.1 115.413,105.24 ; UNIT_G.1 115.413,105.24 ; R4.2 117.582,102.162 115.641,102.162 115.413,102.39 115.413,105.24
USB_IN_2: USB_IN.2 USB_IN.3 | length 2.8
  Top Layer w0.35: USB_IN.3 117.309,162.941 117.309,163.591 USB_IN.2
USB_IN_4: USB_IN.4
VCC: 3V3.1 3V3.2 C3.1 C4.1 C5.1 C6.1 C7.1 C8.1 C9.1 C10.1 C11.1 C12.1 C13.2 LED1.1 LED2.1 LED3.1 LED4.1 LED5.1 LED6.1 LED7.1 LED8.1 LED9.1 MAX7219CWG.19 R1.2 UNIT.3 UNIT_G.2 | length 265.9
  Top Layer w1: LED1.1 114.411,97.763 ; UNIT_G.2 117.736,104.346 117.736,106.164 117.231,106.669 113.806,106.669 113.582,106.893 ; C3.1 117.119,118.898 UNIT.3 112.82,116.431 112.82,107.655 113.582,106.893 ; C4.1@122.258,100.33 122.258,98.974 ; LED2.1 125.507,97.21 ; C5.1@128.1,100.33 128.1,98.974 ; C6.1@133.307,100.33 133.307,99.27 133.307,98.974 ; LED3.1 136.603,97.21 ; LED4.1 147.699,97.763 ; v3(157.504,106.242) 153.373,102.111 153.373,100.33 153.373,100.091 153.373,98.974 153.373,97.924 ; LED5.1 158.795,97.21 ; C8.1@161.247,100.33 161.247,99.27 161.247,98.974 ; C13.2@165.339,109.982 165.339,108.626 166.398,107.568 167.081,107.568 ; R1.2 167.081,107.568 ; LED6.1 169.891,97.763 ; C9.1@172.296,100.33 172.296,98.974 ; 178.9,98.974 172.296,98.974 ; C10.1@178.9,100.33 178.9,99.27 178.9,98.974 179.775,98.974 180.987,97.763 180.987,97.372 ; 3V3.1 3V3.2 184.265,130.071 203.292,130.071 204.886,128.477 204.886,113.488 198.966,107.568 ; LED7.1 180.987,97.372 ; LED8.1 192.083,97.763 ; LED9.1 203.179,97.21 ; C12.1@205.697,100.33 205.697,98.974 204.391,98.974 203.179,97.763 203.179,97.21 ; 113.582,106.893 112.32,105.63 112.32,99.853 114.411,97.763 ; 114.411,97.763 121.046,97.763 122.258,98.974 ; 122.258,98.974 124.023,97.21 125.507,97.21 ; 125.507,97.21 125.507,97.763 126.888,97.763 128.1,98.974 ; 128.1,98.974 133.307,98.974 ; 133.307,98.974 135.072,97.21 136.603,97.21 ; 136.603,97.21 136.603,97.763 147.699,97.763 ; 147.699,97.763 147.86,97.924 153.373,97.924 ; 153.373,97.924 154.639,96.658 158.243,96.658 158.795,97.21 ; 158.795,97.21 158.795,97.763 160.007,98.974 161.247,98.974 ; 161.247,98.974 162.459,97.763 169.891,97.763 ; 167.081,107.568 198.966,107.568 ; 169.891,97.763 171.102,98.974 172.296,98.974 ; 180.987,97.372 181.378,97.763 192.083,97.763 ; 192.083,97.763 197.754,97.763 198.966,98.974 ; 198.966,98.974 198.966,100.33 198.966,101.686 198.966,107.568 ; 198.966,98.974 200.731,97.21 203.179,97.21
  Bottom Layer w1: v3(157.504,106.242) 158.196,106.934 MAX7219CWG.19
VCC_IN_1: D1.2 pad.1 USB_IN.1 VCC_IN.1 VCC_IN.2 VCC_IN.3 VCC_IN.4 | length 43.8
  Top Layer w0.35: D1.2@113.976,155.575 113.976,156.926 111.988,158.914 111.988,161.021 115.207,164.241 USB_IN.1 117.309,164.241 118.549,165.481 pad.1 121.665,166.088 121.665,174.653 VCC_IN.4 VCC_IN.3 VCC_IN.2 VCC_IN.1
VU_1: D2.1 VU.1 VU.2 | length 22.3
  Top Layer w0.35: D2.1@167.57,130.81 167.57,132.161 178.811,143.402 180.057,143.402 180.057,144.653 VU.2@182.597,144.653
WS2812_1: DAT.5 WS2812.1 | length 51.3
  Top Layer w0.35: v2(165.543,151.829) v2(180.66,166.946)
  Bottom Layer w0.35: v2(165.543,151.829) 166.849,150.523 166.849,144.354 166.575,144.08 166.575,142.641 WS2812.1 ; v2(180.66,166.946) 184.248,170.534 184.248,180.604 184.921,181.278 186.866,181.278 DAT.5
pads on no net: AMS1117.1 BAT.2 BUZZER_GPIO4.2 C1.2 C2.2 C3.2 C4.2 C5.2 C6.2 C7.2 C8.2 C9.2 C10.2 C11.2 C12.2 C13.1 C14.2 C15.2 C16.1 C17.1 C18.1 C19.1 C20.2 EN.1 ESP8266_CH340.10 ESP8266_CH340.14 ESP8266_NODEMCU.2 ESP8266_NODEMCU.6 ESP8266_NODEMCU.17 ESP8266_NODEMCU.24 ETA9740.8 ETA9740.9 GND.1 GND.2 GND.3 GND.4 GND.5 GND.6 GND.7 GND.8 GND.9 GND.10 GND_3V3.1 GND_3V3.2 GND_3V3.3 GND_3V3.4 GND_IN.1 GND_IN.2 GND_IN.3 GND_IN.4 LED1.3 LED2.3 LED3.3 LED3V3.1 LED4.3 LED5.3 LED6.3 LED7.3 LED8.3 LED9.3 MAX7219CWG.4 MAX7219CWG.9 R2.2 R3.1 R4.1 R8.1 RST.3 RST.4 T1.1 T2.1 T3.1 T4.1 T5.1 T6.1 T7.1 T8.1 USB_IN.5 USB_IN.6 USB_IN.7 USB_IN.8 USB_IN.9
copper on no net: | length 710.7
  Top Layer w0.5: 113.237,172.085 113.237,166.587 113.308,166.516 ; 113.358,159.366 116.758,159.366 117.384,159.992 117.384,160.401 ; 116.096,89.455 119.263,92.622 120.237,92.622 ; 116.096,134.455 118.814,131.737 123.679,131.737 125.038,133.096 131.914,133.096 136.613,128.397 ; 116.258,161.641 117.384,161.641 117.384,160.401 ; 119.211,93.457 120.237,93.457 120.237,92.622 ; 121.174,108.712 121.174,113.284 122.204,113.284 122.204,113.541 123.32,114.657 v2(125.038,114.657) 130.006,109.689 135.367,109.689 ; 122.272,160.401 117.384,160.401 ; 124.318,100.33 124.318,101.431 124.323,101.436 130.155,101.436 130.16,101.431 ; 125.038,123.317 136.553,123.317 140.236,127 141.449,127 ; 127.606,178.054 130.146,178.054 132.686,178.054 135.226,178.054 ; 130.16,100.33 130.16,101.268 130.16,101.431 ; 130.307,93.457 129.794,93.457 ; 135.367,100.33 135.367,101.431 ; 145.005,175.133 147.545,175.133 150.085,175.133 152.625,175.133 156.774,175.133 161.096,179.455 162.027,178.524 165.345,178.524 ; 152.499,93.457 152.499,92.622 ; 155.433,100.33 155.433,101.431 157.16,101.431 157.265,101.326 ; v2(157.265,97.688) 157.265,101.326 ; 163.279,109.982 162.148,109.982 135.66,109.982 135.367,109.689 ; 163.307,100.33 163.307,101.431 ; 163.595,93.457 163.595,92.622 ; 165.345,175.768 165.345,178.524 ; v2(167.068,102.096) 167.068,101.566 ; 169.727,181.737 168.802,181.737 168.802,180.811 ; 170.786,147.828 172.015,146.599 179.349,146.599 179.587,146.837 180.217,146.837 180.455,146.599 187.337,146.599 188.566,147.828 ; 174.356,100.33 174.356,101.431 ; 177.898,175.006 175.358,175.006 174.607,175.006 168.802,180.811 ; 178.406,124.968 179.578,123.796 187.394,123.796 188.566,124.968 ; 180.438,175.006 182.978,175.006 185.518,175.006 188.058,175.006 190.598,175.006 193.138,175.006 195.678,175.006 198.218,175.006 201.647,175.006 206.096,179.455 ; 180.96,100.33 180.96,101.431 180.831,101.56 174.485,101.56 174.356,101.431 ; 185.787,93.457 185.787,92.622 ; 196.883,93.457 196.883,92.606 ; 201.026,100.33 201.026,101.431 201.031,101.436 207.752,101.436 207.757,101.431 207.757,100.718 207.757,100.33 207.757,99.229 208.989,97.997 208.989,95.318 207.979,94.308 207.979,93.457 207.979,92.606 ; 206.096,89.455 207.979,91.338 207.979,92.606 ; 206.096,134.455 208.215,132.336 208.215,127.084 208.215,118.534 ; 120.237,92.622 128.446,92.622 129.281,93.457 129.794,93.457 ; 129.794,93.457 130.63,92.622 139.542,92.622 140.377,93.457 141.403,93.457 142.429,93.457 143.264,92.622 152.499,92.622 ; 130.16,101.431 130.165,101.436 135.362,101.436 135.367,101.431 ; 135.367,101.431 135.367,109.689 ; 152.499,92.622 152.499,92.606 157.945,92.606 161.096,89.455 163.595,91.954 163.595,92.622 ; 157.265,101.326 157.374,101.436 163.302,101.436 163.307,101.431 ; 163.307,101.431 163.443,101.566 167.068,101.566 ; 163.595,92.622 172.83,92.622 173.665,93.457 174.691,93.457 175.204,93.457 175.717,93.457 176.552,92.622 185.787,92.622 ; 165.345,178.524 166.514,178.524 168.802,180.811 ; 167.068,101.566 174.22,101.566 174.356,101.431 ; 185.787,92.622 185.787,92.606 196.883,92.606 ; 196.883,92.606 207.979,92.606
  Bottom Layer w0.5: 113.308,166.516 113.358,166.516 ; 116.096,89.455 116.096,105.715 v2(125.038,114.657) 125.038,123.317 125.038,133.096 ; 116.096,134.455 113.358,137.193 113.358,159.366 113.358,166.516 ; 127.606,178.054 125.015,180.645 117.286,180.645 116.096,179.455 116.096,167.178 116.758,166.516 113.358,166.516 ; 135.226,178.054 137.794,178.054 137.935,178.195 139.028,178.195 139.036,178.195 141.449,178.195 142.55,178.195 142.55,177.588 145.005,175.133 144.02,174.148 144.02,171.337 145.681,171.337 ; 150.212,158.757 151.988,158.757 152.373,158.757 ; 150.212,167.379 152.625,167.379 ; 152.625,175.133 152.625,173.857 152.625,167.379 ; 154.149,158.757 152.373,158.757 ; v2(157.265,97.688) 157.265,93.286 161.096,89.455 ; 157.591,166.751 158.104,166.751 ; v2(167.068,102.096) 168.096,103.124 169.053,103.124 ; 169.053,109.474 169.791,109.474 178.406,118.089 178.406,119.888 178.406,124.968 ; 170.786,147.828 159.737,158.877 159.223,158.877 ; 177.898,175.006 180.438,175.006 ; 188.566,119.888 188.566,124.968 188.566,147.828 ; 206.096,134.455 206.096,161.166 206.474,161.544 206.096,161.922 206.096,179.455 ; 152.373,158.757 152.373,156.251 152.668,155.956 153.278,155.956 153.837,155.956 156.253,155.956 158.916,158.62 158.916,158.877 159.223,158.877 ; 152.625,167.379 154.149,167.379 157.475,167.379 158.104,166.751 ; 158.104,166.751 158.616,166.751 158.873,166.494 158.873,164.846 160.499,164.846 160.499,164.694 160.499,162.77 159.946,162.217 159.946,158.877 159.223,158.877
  other v1: 112.363,88.188 167.363,88.188 202.363,88.188 112.363,93.188 207.363,98.188 124.087,102.623 129.087,102.623 134.087,102.623 139.087,102.623 202.363,103.188 207.363,103.188 129.087,107.623 134.087,107.623 139.087,107.623 144.087,107.623 202.363,108.188 207.363,108.188 129.087,112.623 134.087,112.623 207.363,113.188 202.4,113.304 112.363,118.188 192.4,118.304 197.4,118.304 112.363,123.188 192.4,123.304 197.4,123.304 202.4,123.304 112.363,128.188 122.363,128.188 152.363,128.188 157.363,128.188 192.4,128.304 197.4,128.304 192.363,133.188 197.363,133.188 202.363,133.188 122.363,138.188 127.363,138.188 132.363,138.188 192.363,138.188 197.363,138.188 202.363,138.188 207.363,138.188 117.363,143.188 112.363,153.188 122.363,153.188 182.363,153.188 187.363,153.188 192.363,153.188 197.363,153.188 202.363,153.188 207.363,153.188 122.363,158.188 127.363,158.188 132.363,158.188 137.363,158.188 142.363,158.188 177.363,158.188 182.363,158.188 187.363,158.188 192.363,158.188 197.363,158.188 202.363,158.188 207.363,158.188 112.363,163.188 122.363,163.188 127.363,163.188 182.363,163.188 192.363,163.188 202.363,163.188 117.363,168.188 127.363,168.188 132.363,168.188 137.363,168.188 187.363,168.188 197.363,168.188 202.363,168.188 207.363,168.188 117.363,173.188 132.363,173.188 142.363,173.188 157.363,173.188 167.363,173.188 172.363,173.188 202.363,173.188 207.363,173.188 112.363,178.188 157.363,178.188 202.363,178.188 117.363,183.188 122.363,183.188 127.363,183.188 132.363,183.188 137.363,183.188 142.363,183.188 147.363,183.188 152.363,183.188 157.363,183.188 162.363,183.188 172.363,183.188 202.363,183.188 207.363,183.188

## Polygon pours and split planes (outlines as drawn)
no net on Top Layer (solid, remove dead copper): 106.016,191.135 215.363,191.135 215.363,77.978 105.381,77.978 103.603,79.756
no net on Bottom Layer (solid, remove dead copper, pour order 4): 105.381,190.754 217.141,190.754 218.157,189.738 218.157,76.2 106.143,76.2 104.365,77.978

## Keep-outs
Board Outline Layer:
  lines w0.254: 211.096,179.455 ccw(c206.096,179.455) 206.096,184.455 116.096,184.455 ccw(c116.096,179.455) 111.096,179.455 111.096,89.455 ccw(c116.096,89.455) 116.096,84.455 206.096,84.455 ccw(c206.096,89.455) 211.096,89.455 211.096,179.455 ; 211.096,179.455 211.096,179.455

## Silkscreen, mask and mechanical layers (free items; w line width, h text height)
Top Silkscreen Layer:
  text "1" at 199.189,182.178 h1.74 r90
  text "5" at 189.029,182.051 h1.74 r90
  text "4" at 191.442,182.051 h1.74 r90
  text "3" at 194.109,182.051 h1.74 r90
  text "2" at 196.649,182.051 h1.74 r90
  text "16" at 176.216,181.955 h1.77 r90
  text "15" at 178.883,181.955 h1.77 r90
  text "14" at 181.423,181.955 h1.77 r90
  text "13" at 183.963,181.955 h1.77 r90
  text "12" at 186.503,181.955 h1.77 r90
  text "5V" at 173.147,179.879 h3 r180
  text "POWER" at 135.75,176.577 h3 r180
  text "A0" at 156.845,176.568 h2.21 r90
  text "LIGHT" at 143.129,175.563 h2.21 r90
  text "3.3V" at 160.704,175.561 h3 r180
  text "5V" at 124.342,164.309 h2.21
  text "GND" at 124.261,159.102 h2.21
  text "SCLK" at 201.79,146.707 h2.21
  text "CS" at 204.225,143.989 h2.21
  text "MISO" at 202.285,141.449 h2.21
  text "MOSI" at 202.285,138.909 h2.21
  text "PWR" at 112.975,112.538 h2.65
  text "UNIT" at 113.157,98.187 h2.65
  text "ESP8266 NodeMCU       Extension V5.0" at 123.873,87.019 h3.98
Bottom Silkscreen Layer:
  text "JLCJLCJLCJLC" at 136.889,153.387 h2.21
  text "Compatible with generic /  ESP8266 modules driven /  by CP2102 chips or /  CH340 chips." at 191.16,138.266 h2.95
  text "Caution! LEDs may become hot!" at 194.018,92.906 h4.42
